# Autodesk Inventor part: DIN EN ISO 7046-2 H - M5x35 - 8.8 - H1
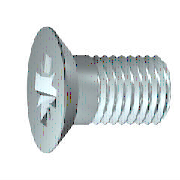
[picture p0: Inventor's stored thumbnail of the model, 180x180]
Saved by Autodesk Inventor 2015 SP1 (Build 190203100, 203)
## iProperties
Created: 2014-02
Part Number: DIN EN ISO 7046-2 H - M5x35 - 8.8 - H1
Material: Stainless Steel, 440C
Description: Countersunk flat head screws (common head style) with type H or type Z cross recess.
Document SubType Name: Modeling
Standard: DIN EN ISO 7046-2 H
Designer: davidvaughan
Standard Revision: 1994
Standards Organization: DIN
Language: en-US
Size Designation: M5x35 - 8.8 - H1
Categories: <MemberInstance><Categories><Category DisplayName="Fasteners" InternalName="e4da775c-781d-43d5-af7c-5136215cf5a6" Mnemonic="FSTN"><Category DisplayName="Bolts"
Density: 7.75 g/cm^3
Appearance: Semi-Polished
IsCustomPart: 1
Author: davidvaughan
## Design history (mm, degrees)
node "Sketch1"
node "WorkPoint1"
node "Sketch2"
node "WorkPoint2"
node "Sketch3"
node "WorkPoint3"
sketch "Sketch4"
  geometry: L1 (-4.65, 0)-(0, 0); L2 (-4.65, -0.55)-(-4.65, 0); L3 (-2.5, -2.7)-(-4.65, -0.55); L4 (-2.5, -3.5)-(-2.5, -2.7); L5 (-2.1, -3.9)-(-2.5, -3.5); L6 (-2.5, -4.7)-(-2.1, -3.9); L7 (-2.5, -35)-(-2.5, -4.7); L8 (0, 0)-(0, -35); L9 (0, 3.339)-(0, -10.7); L10 (0, 3.339)-(0, -10.7); L11 (0, -42.668)-(0, 11.007) reference; L12 (-2.5, -35)-(0, -35); L13 (0.93, 0)-(-5.58, 0) reference
  constraints: 22 end point, 5 vertical, 3 collinear, 1 horizontal, 1 perpendicular
  dimensions: "d3" = 4.65 distance of L1.start L1.end (= 0.5 x Dh); "d5" = 0.8 vertical distance of L6.start L5.start (= msp_x); "d7" = 0.4 horizontal distance of L5.start L4.start (= ParA); "d9" = 0.8 distance of L4.start L3.start (= msp_x); "d11" = 2.7 vertical distance of L3.start L1.start (= ParK); "d13" = 135 deg angle of L4 L3; "d17" = 2.1 horizontal distance of L5.start L1.end (= 0.5 x msp_mdtds); "d19" = 0 horizontal distance of L9.start L1.end; "d51" = 2.5 distance of L7.start L8.end (= 0.5 x NND); "d52" = 35 distance between parallel lines of L12 L1 (= NLG)
node "Sketch6"
workaxis "Work Axis1"
pattern_circular "PolarArray1" dims angle "d31" = 360 deg
node "Sketch8"
workaxis "Work Axis2"
pattern_circular "PolarArray2" dims angle "d40" = 360 deg
fillet "Fillet1" dims "d41" = 1.6 (= 2 x msp_x)
node "MSC_A1"
node "MSC_PF1"
node "MSC_PT1"
body "Solid1"
revolve "Revolution1" stored, may be unused: angle "d20" = 360 deg
sketch "Sketch5"
  geometry: L1 (-2.6, 0)-(0, 0); L2 (-0.433, -2.455)-(-2.6, 0); L3 (0, -2.455)-(-0.433, -2.455); L4 (0, 0)-(0, -2.455); L5 (-2.5, -2.7)-(2.5, -2.7) reference; L6 (-4.65, 0)-(4.65, 0) reference; L7 (0, -3.24)-(0, 0.54) reference
  constraints: 8 end point, 2 collinear, 2 horizontal, 1 vertical
  dimensions: "d22" = 2.6 distance of L1.start L1.end (= 0.5 x M); "d24" = 0.43333 distance of L3.start L2.start (= 0.0833333 x M); "d26" = 2.45455 distance of L1.end L3.start (= 0.909091 x ParK)
extrude "Extrusion1" cut sketch "Sketch5" stored distance "d27" = 0.86667 (= 0.166667 x M); taper "d28" = 0 deg
sketch "Sketch7"
  geometry: L1 (0, -1.35)-(-3.25, 0); L2 (0, 0)-(0, -1.35); L3 (-3.25, 0)-(0, 0); L4 (-2.5, -2.7)-(2.5, -2.7) reference; L5 (0, -3.24)-(0, 0.54) reference; L6 (-4.65, 0)-(4.65, 0) reference
  constraints: 6 end point, 2 collinear, 1 horizontal, 1 vertical
  dimensions: "d33" = 3.25 distance of L1.end L2.start (= 0.625 x M); "d35" = 1.35 distance of L2.start L1.start (= 0.5 x ParK)
extrude "Extrusion2" cut sketch "Sketch7" stored distance "d36" = 0.86667 (= 0.166667 x M); taper "d37" = 0 deg
thread "Thread1" dims "d42" = 10, "d43" = 0
other parameters: "PTC" = 0.8 [user parameter; used in 3 equation terms], "NLG" = 35 [user parameter; used in 1 equation term], "ParK" = 2.7 [user parameter; used in 3 equation terms], "NND" = 5 [user parameter; used in 3 equation terms], "M" = 5.2 [user parameter; used in 5 equation terms], "msp_mdtds" = 4.2 (= NND - PTC) [user parameter; used in 1 equation term], "Dh" = 9.3 [user parameter; used in 1 equation term], "msp_x" = 0.8 (= PTC) [user parameter; used in 3 equation terms], "ParA" = 0.4 (= 0.5 x PTC) [user parameter; used in 1 equation term], "r" = 1.3 [user parameter], "d0" = 3 (derived), "d2" = 5.65 (derived), "d4" = 0.66667 (derived), "d6" = 0.66667 (derived), "d8" = 0.66667 (derived), "d10" = 3.3 (derived), "d12" = 135 deg (derived), "d14" = 14 (derived), "d16" = 2.5 (derived), "d18" = 0 (derived), "d21" = 3.4 (derived), "d23" = 0.56667 (derived), "d25" = 3 (derived), "d32" = 4.25 (derived), "d34" = 1.65 (derived), "d46" = 0, "d47" = 0, "d48" = 0, "d49" = 0, "d50" = 0, "THREADDIA" = 5 (= NND) [user parameter], "TEMPLATE" = 12.345 [user parameter]
